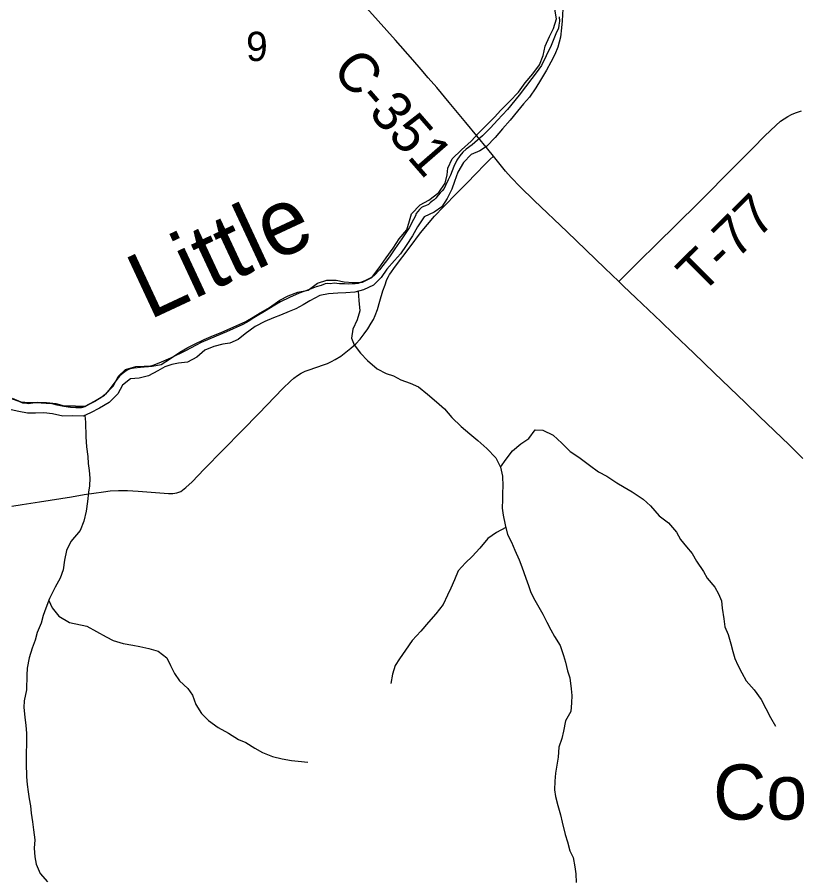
# Model space of a CAD drawing. Extents: x -19.5 to 44.1, y 0 to 22.
# Drawn here: x -14.727 to -13.603, y 7.436 to 8.671 of the extents above; entities that cross this region are included whole.
import ezdxf

# ---------------------------------------------------------------- set-up
doc = ezdxf.new("R2010")
doc.units = 0
for name, color, linetype in [('GM_X_County_Road', 7, 'Continuous'), ('GM_X_County_Road_Text', 7, 'Continuous'), ('GM_X_Major_River', 7, 'Continuous'), ('GM_X_Major_River_Text', 7, 'Continuous'), ('GM_X_Minor_River', 7, 'Continuous'), ('GM_X_Section', 7, 'Continuous'), ('GM_X_Section_Text', 7, 'Continuous'), ('GM_X_Township_Road', 7, 'Continuous'), ('GM_X_Township_Road_Text', 7, 'Continuous'), ('GM_X_Unincorporated_Text', 7, 'Continuous')]:
    doc.layers.add(name, color=color, linetype=linetype)

msp = doc.modelspace()

# ---------------------------------------------------------------- linework, layer by layer
at = {"layer": 'GM_X_County_Road'}
for points in [[(-14.0439, 8.4717), (-14.0519, 8.4816), (-14.0836, 8.5199), (-14.0954, 8.5343), (-14.1073, 8.5486), (-14.1253, 8.5699), (-14.1374, 8.584), (-14.1475, 8.5958), (-14.1597, 8.6099), (-14.1845, 8.6377), (-14.2341, 8.6933)], [(-13.8641, 8.2917), (-13.8845, 8.3112), (-13.9382, 8.363), (-13.9855, 8.4079), (-14.0055, 8.4275), (-14.0184, 8.4408), (-14.0266, 8.4501), (-14.0439, 8.4717)], [(-13.6002, 8.0379), (-13.6202, 8.0575), (-13.6626, 8.0985), (-13.6826, 8.118), (-13.7274, 8.161), (-13.7566, 8.1889), (-13.7857, 8.2169), (-13.8037, 8.2341), (-13.8396, 8.2683), (-13.8576, 8.2854), (-13.8641, 8.2917)]]:
    msp.add_lwpolyline(points, dxfattribs=at)
at = {"layer": 'GM_X_Major_River'}
for points in [[(-13.9447, 8.6827), (-13.9454, 8.6656), (-13.9464, 8.6557), (-13.9478, 8.6421), (-13.9515, 8.6277), (-13.9559, 8.6175), (-13.9619, 8.6063), (-13.9678, 8.595), (-13.9765, 8.5803), (-13.9832, 8.5694), (-13.9922, 8.5563), (-14.0007, 8.5466), (-14.0093, 8.5361), (-14.0199, 8.5231), (-14.0308, 8.5107), (-14.0413, 8.4984), (-14.0537, 8.4854), (-14.0634, 8.4791), (-14.076, 8.474), (-14.0869, 8.4625), (-14.0948, 8.4486), (-14.0997, 8.435), (-14.1037, 8.4244), (-14.1101, 8.4109), (-14.1179, 8.3989), (-14.1291, 8.3911), (-14.1433, 8.3845), (-14.1527, 8.3703), (-14.1602, 8.3571), (-14.1693, 8.3436), (-14.1771, 8.3316), (-14.1857, 8.3219), (-14.1966, 8.3096), (-14.2048, 8.2976), (-14.2161, 8.2864), (-14.2303, 8.2799), (-14.2426, 8.2767), (-14.2555, 8.2755), (-14.2673, 8.2749), (-14.2803, 8.274), (-14.2929, 8.272), (-14.3071, 8.2643), (-14.3167, 8.2584), (-14.3271, 8.2529), (-14.3367, 8.249), (-14.3494, 8.2435), (-14.3594, 8.2399), (-14.3716, 8.2345), (-14.3855, 8.2275), (-14.3998, 8.2168), (-14.4098, 8.2086), (-14.4221, 8.2035), (-14.4317, 8.2018), (-14.445, 8.1987), (-14.4577, 8.1932), (-14.4693, 8.1832), (-14.4828, 8.1763), (-14.4954, 8.1746), (-14.5049, 8.1729), (-14.5153, 8.1697), (-14.5253, 8.1638), (-14.5387, 8.1565), (-14.5521, 8.1533), (-14.5643, 8.1521), (-14.5759, 8.1432), (-14.5823, 8.1308), (-14.5947, 8.1185), (-14.6086, 8.1104), (-14.6216, 8.1034), (-14.632, 8.0987), (-14.6468, 8.0994)], [(-14.6431, 8.113), (-14.6291, 8.1131), (-14.616, 8.1204), (-14.6017, 8.1289), (-14.5889, 8.1423), (-14.5821, 8.1555), (-14.5713, 8.1659), (-14.5567, 8.1698), (-14.5449, 8.1703), (-14.5331, 8.1704), (-14.5202, 8.1728), (-14.507, 8.1813), (-14.4935, 8.1905), (-14.482, 8.1971), (-14.4724, 8.2019), (-14.4589, 8.2088), (-14.4455, 8.2143), (-14.4344, 8.2186), (-14.4248, 8.223), (-14.4129, 8.2281), (-14.399, 8.2346), (-14.3883, 8.2409), (-14.3782, 8.2467), (-14.3651, 8.2548), (-14.3501, 8.2652), (-14.3382, 8.2714), (-14.3244, 8.2764), (-14.3098, 8.2792), (-14.2963, 8.2896), (-14.2829, 8.2939), (-14.2696, 8.2936), (-14.2579, 8.2915), (-14.2449, 8.2904), (-14.2316, 8.2909), (-14.2182, 8.2975), (-14.2076, 8.3114), (-14.1978, 8.3256), (-14.1876, 8.3395), (-14.179, 8.353), (-14.1681, 8.3657), (-14.1644, 8.3789), (-14.1615, 8.3887), (-14.1491, 8.4018), (-14.1364, 8.4087), (-14.1224, 8.4195), (-14.1134, 8.433), (-14.1105, 8.4447), (-14.1092, 8.4545), (-14.1032, 8.4677), (-14.09, 8.4808), (-14.076, 8.493), (-14.0644, 8.5053), (-14.0523, 8.5176), (-14.0426, 8.5277), (-14.0333, 8.5374), (-14.0208, 8.5501), (-14.008, 8.5631), (-13.9986, 8.5766), (-13.9877, 8.5897), (-13.9779, 8.6024), (-13.9727, 8.616), (-13.9698, 8.6292), (-13.9638, 8.6432), (-13.9578, 8.6548), (-13.9534, 8.6684), (-13.9561, 8.6825)], [(-14.6431, 8.113), (-14.6587, 8.1133), (-14.6708, 8.1166), (-14.6848, 8.118), (-14.6974, 8.1183), (-14.7103, 8.1181), (-14.7209, 8.1187), (-14.7337, 8.1239)], [(-14.6468, 8.0994), (-14.6613, 8.0989), (-14.676, 8.1019), (-14.6885, 8.1036), (-14.7007, 8.1031), (-14.7121, 8.103), (-14.7245, 8.1055), (-14.7355, 8.108)]]:
    msp.add_lwpolyline(points, dxfattribs=at)
at = {"layer": 'GM_X_Minor_River'}
for points in [[(-14.238, 8.2779), (-14.2371, 8.2648), (-14.2357, 8.25), (-14.2393, 8.2367), (-14.2455, 8.2235), (-14.2475, 8.2106), (-14.2438, 8.2011), (-14.2348, 8.1889), (-14.2243, 8.1785), (-14.2108, 8.1666), (-14.1979, 8.16), (-14.1873, 8.1565), (-14.1767, 8.1511), (-14.1635, 8.146), (-14.1514, 8.141), (-14.1386, 8.1302), (-14.1254, 8.1191), (-14.1141, 8.1091), (-14.1036, 8.0968), (-14.0901, 8.0842), (-14.078, 8.0734), (-14.0664, 8.0638), (-14.0536, 8.0523), (-14.0404, 8.0389), (-14.0337, 8.0256), (-14.0312, 8.0126), (-14.0306, 7.9982), (-14.031, 7.9887), (-14.0311, 7.9792), (-14.0316, 7.9667), (-14.0298, 7.9568), (-14.0273, 7.9431), (-14.024, 7.929), (-14.0181, 7.918), (-14.0132, 7.9069), (-14.0073, 7.8928), (-14.0032, 7.8829), (-13.9977, 7.8665), (-13.9936, 7.8559), (-13.9903, 7.846), (-13.9847, 7.8349), (-13.9787, 7.825), (-13.9731, 7.8147), (-13.9676, 7.8036), (-13.9616, 7.7926), (-13.9564, 7.783), (-13.9485, 7.77), (-13.9434, 7.7556), (-13.9408, 7.7461), (-13.9379, 7.7335), (-13.9346, 7.7236), (-13.9324, 7.708), (-13.9314, 7.6981), (-13.9319, 7.6879), (-13.9331, 7.6754), (-13.9409, 7.6622), (-13.9433, 7.647), (-13.9457, 7.6368), (-13.9504, 7.624), (-13.9513, 7.6099), (-13.9529, 7.5982), (-13.9549, 7.5872), (-13.9561, 7.5754), (-13.9563, 7.5633), (-13.9552, 7.5534), (-13.9519, 7.5405), (-13.9479, 7.5272), (-13.9453, 7.5165), (-13.941, 7.499), (-13.9376, 7.4884), (-13.9344, 7.4758), (-13.9299, 7.4659), (-13.9274, 7.4526), (-13.9259, 7.4427), (-13.9253, 7.4302)], [(-14.63, 8.0996), (-14.6288, 8.0902), (-14.6283, 8.069), (-14.6276, 8.0549), (-14.6255, 8.0409), (-14.6248, 8.031), (-14.6234, 8.0211), (-14.6228, 8.0101), (-14.6233, 7.9991), (-14.6245, 7.9896), (-14.6261, 7.9763), (-14.6278, 7.9627), (-14.6314, 7.9483), (-14.6364, 7.9347), (-14.6498, 7.9189)], [(-14.0337, 8.0256), (-14.0256, 8.0372), (-14.0168, 8.0489), (-14.0045, 8.0591), (-13.993, 8.0669), (-13.9842, 8.079), (-13.9732, 8.0785), (-13.9584, 8.0715), (-13.946, 8.06), (-13.934, 8.0481), (-13.9216, 8.04), (-13.9065, 8.0285), (-13.8933, 8.0189), (-13.8816, 8.0127), (-13.8672, 8.0034), (-13.8567, 7.9972), (-13.8453, 7.9903), (-13.8295, 7.9799), (-13.819, 7.9703), (-13.8066, 7.9561), (-13.793, 7.9458), (-13.7814, 7.9324), (-13.7758, 7.9221), (-13.7672, 7.9113), (-13.7593, 7.9018), (-13.7529, 7.8907), (-13.7428, 7.8762), (-13.7376, 7.8666), (-13.7267, 7.8536), (-13.7211, 7.8441), (-13.717, 7.8338), (-13.716, 7.8235), (-13.7135, 7.8083), (-13.7121, 7.7966), (-13.7076, 7.7859), (-13.7036, 7.7726), (-13.701, 7.7615), (-13.6977, 7.7513), (-13.6937, 7.7417), (-13.6881, 7.7307), (-13.6817, 7.7192), (-13.6701, 7.7062), (-13.66, 7.6924), (-13.6533, 7.6799), (-13.6469, 7.6669), (-13.6395, 7.6543)], [(-14.0264, 7.9391), (-14.0396, 7.9319), (-14.0518, 7.9232), (-14.0637, 7.9097), (-14.0745, 7.8977), (-14.084, 7.8886), (-14.0944, 7.877), (-14.0999, 7.8641), (-14.1053, 7.8524), (-14.1099, 7.8422), (-14.1161, 7.829), (-14.1265, 7.8154), (-14.1373, 7.8034), (-14.148, 7.7906), (-14.1607, 7.7771), (-14.17, 7.7635), (-14.1788, 7.7511), (-14.185, 7.7412), (-14.1885, 7.7291), (-14.1913, 7.7155)], [(-14.6498, 7.9189), (-14.656, 7.906), (-14.6591, 7.8924), (-14.6608, 7.8784), (-14.6651, 7.8663), (-14.6724, 7.8534), (-14.6805, 7.8372), (-14.6856, 7.8236), (-14.6895, 7.813), (-14.6926, 7.802), (-14.698, 7.7884), (-14.7012, 7.7778), (-14.7054, 7.7661), (-14.7094, 7.7521), (-14.7125, 7.7377), (-14.713, 7.7274), (-14.7132, 7.7066), (-14.7168, 7.6906), (-14.7173, 7.6812), (-14.7159, 7.6671), (-14.7145, 7.6553), (-14.7134, 7.6443), (-14.7132, 7.6303), (-14.7137, 7.6143), (-14.7139, 7.6014), (-14.7133, 7.5817), (-14.7123, 7.5707), (-14.7112, 7.56), (-14.7098, 7.5501), (-14.7076, 7.5399), (-14.7066, 7.5296), (-14.7048, 7.5171), (-14.7034, 7.5057), (-14.7017, 7.4916), (-14.7022, 7.4795), (-14.7015, 7.4669), (-14.6994, 7.4563), (-14.6938, 7.4433), (-14.6833, 7.4311)], [(-14.6816, 7.8343), (-14.6765, 7.8242), (-14.6671, 7.812), (-14.6516, 7.8029)], [(-14.6516, 7.8029), (-14.6268, 7.7976), (-14.6132, 7.7899), (-14.5992, 7.7825), (-14.589, 7.7771), (-14.575, 7.7728), (-14.561, 7.7704), (-14.5511, 7.7684), (-14.5382, 7.7656), (-14.5246, 7.762), (-14.5122, 7.7521), (-14.507, 7.7414), (-14.501, 7.7299), (-14.4939, 7.7192), (-14.4819, 7.7085), (-14.4755, 7.6989), (-14.4707, 7.6852), (-14.4625, 7.6723), (-14.4523, 7.6627), (-14.4384, 7.6523), (-14.4236, 7.6442), (-14.4097, 7.6353), (-14.3991, 7.6307), (-14.3859, 7.6229), (-14.3749, 7.6168), (-14.3609, 7.6109), (-14.3469, 7.6074), (-14.3337, 7.605), (-14.3238, 7.6041), (-14.3101, 7.6028)]]:
    msp.add_lwpolyline(points, dxfattribs=at)
at = {"layer": 'GM_X_Section'}
msp.add_lwpolyline([(-13.9498, 8.6711), (-13.9491, 8.665), (-13.9503, 8.6593), (-13.9507, 8.6552), (-13.9543, 8.6469), (-13.9613, 8.6303), (-13.9683, 8.6153), (-13.9753, 8.6017), (-13.9826, 8.5912), (-13.9888, 8.583), (-14.0073, 8.559), (-14.0238, 8.5384), (-14.0381, 8.523), (-14.0484, 8.5122), (-14.0599, 8.5006), (-14.0745, 8.4879), (-14.0833, 8.4816), (-14.0879, 8.4771), (-14.0921, 8.4718), (-14.0964, 8.4658), (-14.1007, 8.4568), (-14.1057, 8.4444), (-14.1089, 8.4376), (-14.1127, 8.4297), (-14.1147, 8.4252), (-14.1174, 8.4218), (-14.1205, 8.4188), (-14.1232, 8.4158), (-14.1266, 8.4113), (-14.1289, 8.4091), (-14.132, 8.4069), (-14.1347, 8.4046), (-14.1373, 8.4024), (-14.1415, 8.4005), (-14.1442, 8.3994), (-14.1469, 8.398), (-14.1499, 8.3953), (-14.1526, 8.392), (-14.1546, 8.3893), (-14.1557, 8.386), (-14.1585, 8.3807), (-14.1647, 8.369), (-14.1755, 8.3529), (-14.1855, 8.3386), (-14.1929, 8.3274), (-14.199, 8.3191), (-14.2071, 8.3086), (-14.2144, 8.3011), (-14.2179, 8.2982), (-14.2224, 8.2959), (-14.2274, 8.2934), (-14.2323, 8.2912), (-14.2377, 8.289), (-14.2422, 8.2883), (-14.2464, 8.2883), (-14.2513, 8.288), (-14.2577, 8.2885), (-14.2649, 8.2885), (-14.2725, 8.2894), (-14.2774, 8.2887), (-14.282, 8.2888), (-14.2854, 8.2884), (-14.2911, 8.2862), (-14.2979, 8.2844), (-14.3075, 8.2804), (-14.3227, 8.2753), (-14.3364, 8.269), (-14.3493, 8.2628), (-14.3574, 8.2579), (-14.37, 8.2505), (-14.3875, 8.2398), (-14.3948, 8.235), (-14.4035, 8.2302), (-14.4268, 8.2198), (-14.4508, 8.2099), (-14.463, 8.2044), (-14.4843, 8.193), (-14.5068, 8.1819), (-14.5239, 8.1749), (-14.5323, 8.1712), (-14.5392, 8.1694), (-14.5498, 8.1684), (-14.5592, 8.1678), (-14.5646, 8.1667), (-14.5691, 8.1649), (-14.5726, 8.1623), (-14.5764, 8.1593), (-14.5802, 8.156), (-14.5852, 8.1496), (-14.5933, 8.1383), (-14.6003, 8.1305), (-14.6052, 8.126), (-14.6155, 8.1197), (-14.6239, 8.1153), (-14.6297, 8.1123), (-14.635, 8.1105), (-14.6429, 8.1106), (-14.6503, 8.1113), (-14.6597, 8.1126), (-14.6696, 8.1146), (-14.6767, 8.1163), (-14.6851, 8.1168), (-14.6926, 8.1176), (-14.7009, 8.1178), (-14.7108, 8.1164), (-14.7153, 8.1172), (-14.7187, 8.1176), (-14.724, 8.1196), (-14.7335, 8.1233)], dxfattribs=at)
at = {"layer": 'GM_X_Township_Road'}
for points in [[(-13.8641, 8.2917), (-13.8612, 8.2946), (-13.8349, 8.321), (-13.8106, 8.345), (-13.751, 8.4039), (-13.6963, 8.4588), (-13.6722, 8.483), (-13.6547, 8.5005), (-13.6392, 8.5157), (-13.6323, 8.5217), (-13.6273, 8.5253), (-13.6221, 8.5285), (-13.6166, 8.5311), (-13.6109, 8.5335), (-13.6022, 8.5366)], [(-14.7346, 7.9699), (-14.7195, 7.9722), (-14.6948, 7.9762), (-14.6643, 7.9807), (-14.649, 7.9833), (-14.6306, 7.9863), (-14.603, 7.9905), (-14.5937, 7.9916), (-14.5813, 7.9922), (-14.5688, 7.992), (-14.5533, 7.9912), (-14.5285, 7.9893), (-14.5099, 7.988), (-14.5038, 7.988), (-14.5008, 7.9883), (-14.4978, 7.9888), (-14.495, 7.9898), (-14.4923, 7.991), (-14.4897, 7.9926), (-14.485, 7.9964), (-14.4759, 8.0048), (-14.4586, 8.0226), (-14.4043, 8.0782), (-14.3804, 8.1026), (-14.3458, 8.1383), (-14.3347, 8.1492), (-14.33, 8.1533), (-14.3249, 8.157), (-14.3195, 8.1603), (-14.3139, 8.1631), (-14.3081, 8.1654), (-14.2874, 8.1722), (-14.2817, 8.1744), (-14.2761, 8.177), (-14.2707, 8.18), (-14.263, 8.185), (-14.2555, 8.1905), (-14.2482, 8.1963), (-14.2414, 8.2026), (-14.2351, 8.2093), (-14.2294, 8.2166), (-14.2241, 8.2242), (-14.2191, 8.232), (-14.2161, 8.2374), (-14.2136, 8.243), (-14.2103, 8.2516), (-14.2067, 8.2635), (-14.2024, 8.2784), (-14.1994, 8.2873), (-14.1973, 8.2931), (-14.1962, 8.2958), (-14.1946, 8.2989), (-14.1929, 8.3017), (-14.1912, 8.3042), (-14.1856, 8.3118), (-14.1632, 8.3416), (-14.1484, 8.3615), (-14.1386, 8.3737), (-14.1284, 8.3854), (-14.1156, 8.399), (-14.096, 8.4189), (-14.0813, 8.434), (-14.0699, 8.4457), (-14.0559, 8.4601), (-14.0491, 8.4667), (-14.0439, 8.4717)]]:
    msp.add_lwpolyline(points, dxfattribs=at)

# ---------------------------------------------------------------- texts
at = {"layer": 'GM_X_County_Road_Text'}
msp.add_text('C-351', height=0.05682, rotation=311.0123, dxfattribs=at).set_placement((-14.2771, 8.5942))
at = {"layer": 'GM_X_Major_River_Text'}
msp.add_text('Little', height=0.09471, rotation=25.0206, dxfattribs=at).set_placement((-14.5379, 8.2362))
at = {"layer": 'GM_X_Section_Text'}
msp.add_text('9', height=0.0419, rotation=0, dxfattribs=at).set_placement((-14.3987, 8.608))
at = {"layer": 'GM_X_Township_Road_Text'}
msp.add_text('T-77', height=0.05682, rotation=44.7495, dxfattribs=at).set_placement((-13.7462, 8.2719))
at = {"layer": 'GM_X_Unincorporated_Text'}
msp.add_text('Cortsville', height=0.07898, rotation=0, dxfattribs=at).set_placement((-13.7291, 7.5204))

doc.saveas('drawing.dxf')
